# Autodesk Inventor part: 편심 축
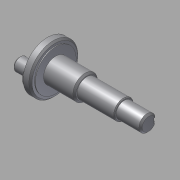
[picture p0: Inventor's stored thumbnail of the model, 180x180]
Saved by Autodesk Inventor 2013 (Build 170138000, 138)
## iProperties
Created: 2015-10
Part Number: 편심 축
Document SubType Name: Modeling
Designer: mdu
Density: 1 g/cm^3
Material: 강철, 연강
Mass: 10.9708 g
Surface Area: 42.7652 cm^2
Volume: 10.9708 cm^3
Author: mdu
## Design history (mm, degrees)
sketch "스케치1"
  geometry: L1 (1.75, -12.001)-(1.75, 11.999) reference; L2 (-16.95, -14)-(-16.95, 14) reference; L3 (-36.25, -18.06)-(-36.25, 18.06) reference; L4 (-41.25, 0)-(20.75, 0); L5 (-41.25, 0)-(-41.25, 15); L6 (-41.25, 15)-(-36.25, 15); L7 (-36.25, 15)-(-36.25, 7.5); L8 (-36.25, 7.5)-(-17.25, 7.5); L9 (-17.25, 6)-(5.75, 6); L10 (20.75, 5)-(20.75, 0); L11 (5.75, 6)-(5.75, 5); L12 (5.75, 5)-(20.75, 5); L13 (-17.25, -13.7)-(-17.25, 13.7) reference; L14 (-17.25, 7.5)-(-17.25, 6); 2 further points
  constraints: 20 end point, 7 perpendicular, 5 point on line, 1 collinear, 1 midpoint, 1 parallel
  dimensions: "d0" = 12 diameter of L9 L4; "d1" = 15 diameter of L8 L4; "d2" = 30 diameter of L6 L4; "d3" = 5 distance of L5.end L6.end; "d4" = 62 distance of L4.start L4.end; "d5" = 10 diameter of L12 L4; "d6" = 15 distance of L11.end L10.start
revolve "회전1" sketch "스케치1" stored, may be unused: angle "d7" = 90 deg
sketch "스케치4"
  geometry: C1 r 15 at (0, 0) reference; C2 r 12.5 at (0, 0); 1 further point
  constraints: 1 centre point, 1 coincident
  dimensions: "d24" = 25 diameter of C2
extrude "돌출4" cut sketch "스케치4" distance "d25" = 0.5; taper "d26" = 0 deg
sketch "스케치2"
  geometry: C1 r 4 at (0, -7.5); C2 r 7.5 at (0, -7.5); C3 r 15 at (0, 0) reference; 1 further point
  constraints: 2 centre point, 1 coincident, 1 tangent, 1 vertical alignment
  dimensions: "d8" = 8 diameter of C1; "d9" = 7.5 distance of point (0, 0) C1.centre
extrude "돌출1" join sketch "스케치2" distance "d10" = 10; taper "d11" = 0 deg
extrude "돌출2" join sketch "스케치2" distance "d12" = 0.5; taper "d13" = 0 deg
node "작업 평면1"
sketch "스케치3"
  geometry: L1 (-7.5, 5)-(-7.5, -5) reference; L2 (-7.5, 1.5)-(3, 1.5); L3 (3, -1.5)-(-7.5, -1.5); A1 r 1.5 centre (3, 0) between (3, -1.5) and (3, 1.5); 2 further points
  constraints: 4 end point, 2 perpendicular, 2 point on circle, 2 point on line, 2 tangent, 1 centre point, 1 horizontal alignment, 1 midpoint
  dimensions: "d14" = 3 distance between parallel lines of L3 L2; "d15" = 12 dimension on A1 L1
extrude "돌출3" cut sketch "스케치3" distance "d16" = 1.8; taper "d17" = 0 deg
chamfer "모따기1" distance "d18" = 1; stored, may be unused: second distance "d19" = 2, angle "d20" = 45 deg
chamfer "모따기2" distance "d21" = 0.5; stored, may be unused: second distance "d22" = 2, angle "d23" = 45 deg
node "솔리드1"
node "참조1"
node "참조2"
node "참조3"
node "참조4"
